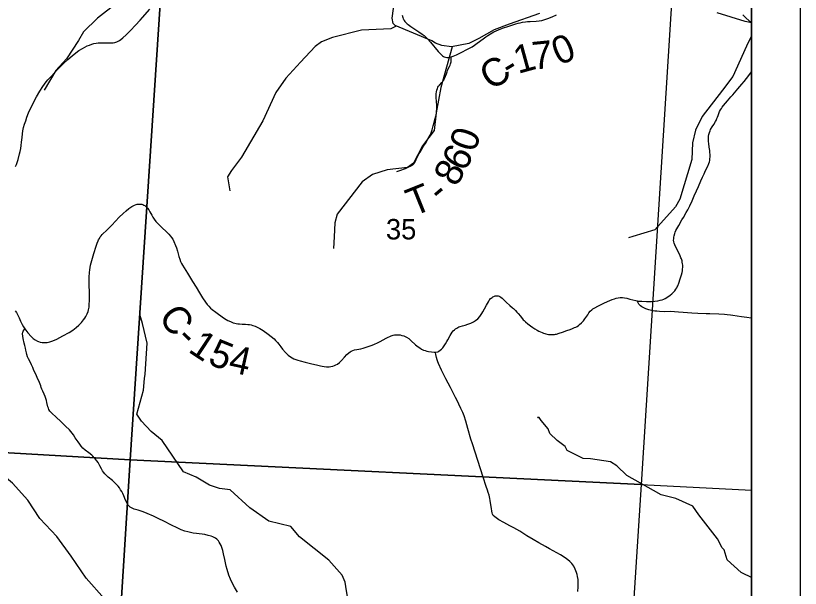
# Model space of a CAD drawing. Extents: x -2.1 to 31.9, y 6.3 to 28.3.
# Drawn here: x 5.327 to 6.934, y 23.525 to 24.699 of the extents above; entities that cross this region are included whole.
import ezdxf

# ---------------------------------------------------------------- set-up
doc = ezdxf.new("R2010")
doc.units = 0
for name, color, linetype in [('Default', 7, 'Continuous'), ('GM_X_County_Road', 7, 'Continuous'), ('GM_X_County_Road_Text', 7, 'Continuous'), ('GM_X_Minor_River', 7, 'Continuous'), ('GM_X_Section', 7, 'Continuous'), ('GM_X_Section_Text', 7, 'Continuous'), ('GM_X_Township_Road', 7, 'Continuous'), ('GM_X_Township_Road_Text', 7, 'Continuous'), ('SH_Cut_Line', 7, 'Continuous'), ('SH_Data', 7, 'Continuous')]:
    doc.layers.add(name, color=color, linetype=linetype)

msp = doc.modelspace()

# ---------------------------------------------------------------- linework, layer by layer
at = {"layer": 'Default'}
msp.add_lwpolyline([(6.8344, 20.444), (6.8344, 25.7721), (5.5694, 25.8349), (4.6286, 25.8765), (4.6032, 25.4816), (4.5667, 24.9084), (4.5473, 24.5954), (4.4901, 23.6442), (4.4651, 23.2405)], dxfattribs=at)
msp.add_lwpolyline([(6.8344, 23.7263), (6.8344, 24.7715), (6.674, 24.7794), (6.6083, 23.7379)], close=True, dxfattribs=at)
at = {"layer": 'GM_X_County_Road'}
for points in [[(5.3265, 24.3899), (5.3282, 24.3943), (5.3315, 24.4045), (5.3346, 24.416), (5.3358, 24.4209), (5.337, 24.4268), (5.3379, 24.4331), (5.3388, 24.4399), (5.3398, 24.4493), (5.3406, 24.4571), (5.3413, 24.4628), (5.3421, 24.4667), (5.3428, 24.47), (5.3448, 24.4766), (5.3472, 24.4837), (5.3497, 24.4911), (5.3529, 24.4997), (5.3554, 24.5059), (5.3588, 24.5126), (5.3623, 24.5197), (5.3694, 24.5331), (5.376, 24.5443), (5.3823, 24.5543), (5.3855, 24.5591), (5.3888, 24.5634), (5.3924, 24.5676), (5.399, 24.5746), (5.4125, 24.5887), (5.4251, 24.6016), (5.4337, 24.6096), (5.4421, 24.6169), (5.4498, 24.6232), (5.4562, 24.6277), (5.4635, 24.6322), (5.4686, 24.6349), (5.4734, 24.6372), (5.478, 24.6389), (5.4825, 24.6405), (5.4868, 24.6418), (5.4912, 24.6428), (5.4953, 24.6432), (5.4996, 24.6435), (5.5062, 24.6435), (5.5186, 24.6432), (5.5234, 24.6432), (5.5266, 24.6434), (5.5297, 24.644), (5.5319, 24.6446), (5.5341, 24.6456), (5.5364, 24.6467), (5.5392, 24.6483), (5.5421, 24.6504), (5.5459, 24.6535), (5.5529, 24.6601), (5.5617, 24.6687), (5.5723, 24.6797), (5.5814, 24.6897), (5.5863, 24.6954), (5.6013, 24.7128)], [(6.1184, 24.7002), (6.1202, 24.6951), (6.1209, 24.693), (6.1219, 24.691), (6.123, 24.6891), (6.1242, 24.6873), (6.1254, 24.6858), (6.1269, 24.6842), (6.1285, 24.6826), (6.1306, 24.6809), (6.1361, 24.6769), (6.1427, 24.6726), (6.1529, 24.6662), (6.1595, 24.6616), (6.1639, 24.6582), (6.1671, 24.6554), (6.1715, 24.6511), (6.1768, 24.6451), (6.1925, 24.6258), (6.1971, 24.6207), (6.1993, 24.6186), (6.2012, 24.617), (6.2031, 24.6158), (6.2049, 24.615), (6.2074, 24.6142), (6.2099, 24.6137), (6.2126, 24.6137), (6.2158, 24.6141), (6.2192, 24.6149), (6.2231, 24.6163), (6.2296, 24.6191), (6.2368, 24.6223), (6.2551, 24.6317), (6.2617, 24.6352), (6.267, 24.6385), (6.2726, 24.6425), (6.2844, 24.6517), (6.2898, 24.6558), (6.2939, 24.6586), (6.2996, 24.6621), (6.3067, 24.6658), (6.3157, 24.6699), (6.3244, 24.6733), (6.3372, 24.6779), (6.3513, 24.6826), (6.3561, 24.6839), (6.3604, 24.6848), (6.3652, 24.6857), (6.3712, 24.6867), (6.3755, 24.687), (6.3811, 24.6874), (6.3929, 24.6876), (6.3992, 24.6883), (6.4047, 24.6894), (6.4108, 24.6911), (6.4172, 24.6934), (6.4259, 24.6971), (6.4349, 24.7012)], [(6.8165, 24.7006), (6.823, 24.6946), (6.8298, 24.6886), (6.8344, 24.685)], [(6.1869, 24.0096), (6.1877, 24.0096), (6.1914, 24.0104), (6.1939, 24.0115), (6.1966, 24.0132), (6.1992, 24.0156), (6.2018, 24.0186), (6.2048, 24.0226), (6.2076, 24.0268), (6.2101, 24.031), (6.2123, 24.0347), (6.2171, 24.0438), (6.2192, 24.0471), (6.2211, 24.0502), (6.2233, 24.053), (6.2255, 24.0552), (6.2276, 24.057), (6.2303, 24.0589), (6.2326, 24.0602), (6.2348, 24.0611), (6.2376, 24.0621), (6.2421, 24.0635), (6.2477, 24.065), (6.2531, 24.0665), (6.2594, 24.0689), (6.2649, 24.0715), (6.269, 24.0741), (6.2733, 24.0775), (6.2778, 24.0824), (6.282, 24.0884), (6.2839, 24.0919), (6.2874, 24.0981), (6.2913, 24.1057), (6.2952, 24.1128), (6.2971, 24.1157), (6.2984, 24.1174), (6.2999, 24.1191), (6.3012, 24.1203), (6.3028, 24.1217), (6.3045, 24.1227), (6.3062, 24.1236), (6.3077, 24.1243), (6.3093, 24.1248), (6.3106, 24.125), (6.312, 24.1251), (6.3131, 24.1251), (6.3142, 24.125), (6.3156, 24.1248), (6.3171, 24.1243), (6.3188, 24.1235), (6.3207, 24.1222), (6.3233, 24.1199), (6.3261, 24.1174), (6.3318, 24.1116), (6.3392, 24.1049), (6.3445, 24.1004), (6.3465, 24.0987), (6.3486, 24.0967), (6.3506, 24.0948), (6.3535, 24.0916), (6.3563, 24.0885), (6.3608, 24.0831), (6.3667, 24.0759), (6.3685, 24.074), (6.3714, 24.0713), (6.376, 24.0674), (6.3814, 24.0633), (6.3862, 24.0601), (6.3906, 24.0572), (6.3949, 24.0547), (6.3986, 24.0527), (6.4053, 24.0495), (6.4081, 24.0484), (6.411, 24.0474), (6.4131, 24.0468), (6.4158, 24.0463), (6.4183, 24.0459), (6.421, 24.0456), (6.424, 24.0454), (6.4271, 24.0454), (6.4305, 24.0457), (6.4326, 24.046), (6.4349, 24.0466), (6.4403, 24.0483), (6.4471, 24.0506), (6.4558, 24.0536), (6.4627, 24.0561), (6.4673, 24.0578), (6.472, 24.0597), (6.4744, 24.0608), (6.4771, 24.0623), (6.4797, 24.0639), (6.4823, 24.0659), (6.4863, 24.0694), (6.4899, 24.0735), (6.4929, 24.0774), (6.4987, 24.086), (6.5013, 24.0901), (6.5039, 24.0934), (6.5069, 24.096), (6.5094, 24.0979), (6.5136, 24.1005), (6.5196, 24.1036), (6.5238, 24.1056), (6.5321, 24.1096), (6.5394, 24.1132), (6.5486, 24.1171), (6.5536, 24.119), (6.5573, 24.12), (6.5611, 24.1209), (6.5653, 24.1214), (6.5704, 24.1212), (6.5741, 24.1207), (6.5792, 24.1198), (6.5854, 24.1183), (6.5915, 24.1167), (6.5974, 24.1152), (6.6004, 24.1146), (6.6026, 24.1142), (6.6096, 24.1136), (6.6191, 24.113), (6.6237, 24.113), (6.6298, 24.1131), (6.6365, 24.1137), (6.6428, 24.1149), (6.6471, 24.1158), (6.6512, 24.1169), (6.6547, 24.1182), (6.6576, 24.1197), (6.6608, 24.1215), (6.6678, 24.1263), (6.6711, 24.1291), (6.6736, 24.1314), (6.677, 24.1352), (6.6796, 24.1387), (6.6811, 24.141), (6.6823, 24.1435), (6.6834, 24.1457), (6.6853, 24.1505), (6.6884, 24.1597), (6.6911, 24.1681), (6.6923, 24.1726), (6.6928, 24.1759), (6.6932, 24.1794), (6.6935, 24.1835), (6.6935, 24.1877), (6.6932, 24.1906), (6.6926, 24.194), (6.6921, 24.1964), (6.6916, 24.1984), (6.6907, 24.2009), (6.6897, 24.2031), (6.6873, 24.2086), (6.6836, 24.2161), (6.6774, 24.2293), (6.676, 24.233), (6.6753, 24.2354), (6.6749, 24.239), (6.6751, 24.242), (6.6754, 24.2449), (6.676, 24.2482), (6.6774, 24.2527), (6.6782, 24.2556), (6.6794, 24.2585), (6.6813, 24.2623), (6.6854, 24.2693), (6.6917, 24.2804), (6.6948, 24.2856), (6.7005, 24.2954), (6.7038, 24.3014), (6.7059, 24.3055), (6.7078, 24.3095), (6.7125, 24.3196), (6.7171, 24.3296), (6.7218, 24.3402), (6.7257, 24.3489), (6.7307, 24.3605), (6.7342, 24.3684), (6.7373, 24.3748), (6.7405, 24.3817), (6.7447, 24.391), (6.7469, 24.3961), (6.7481, 24.3995), (6.7488, 24.4026), (6.7493, 24.4059), (6.7495, 24.4096), (6.7495, 24.4138), (6.7493, 24.4192), (6.7488, 24.4229), (6.7477, 24.4297), (6.7467, 24.4368), (6.7463, 24.441), (6.7461, 24.4448), (6.7461, 24.4477), (6.7465, 24.4525), (6.7469, 24.4553), (6.7481, 24.4597), (6.7494, 24.4631), (6.7507, 24.466), (6.7537, 24.4711), (6.7569, 24.4764), (6.7604, 24.482), (6.7619, 24.4846), (6.7636, 24.4884), (6.7647, 24.4911), (6.7659, 24.4947), (6.7672, 24.4983), (6.7682, 24.5005), (6.769, 24.5025), (6.7707, 24.506), (6.7728, 24.5092), (6.7746, 24.5119), (6.7772, 24.5153), (6.7851, 24.5247), (6.7923, 24.5327), (6.7963, 24.5372), (6.8063, 24.5493), (6.8149, 24.5591), (6.8196, 24.5642), (6.8244, 24.5701), (6.8313, 24.5796), (6.8344, 24.5839)], [(5.3255, 24.0943), (5.3283, 24.0905), (5.331, 24.0854), (5.3336, 24.0797), (5.3367, 24.0727), (5.3398, 24.0663), (5.3424, 24.0615), (5.3451, 24.0573), (5.3515, 24.0491), (5.358, 24.0418), (5.3625, 24.0376), (5.3664, 24.0348), (5.3711, 24.0322), (5.3736, 24.0311), (5.3767, 24.0301), (5.3806, 24.0292), (5.3848, 24.0291), (5.3883, 24.0292), (5.3912, 24.0295), (5.3965, 24.0307), (5.4029, 24.0327), (5.4107, 24.0363), (5.4229, 24.0426), (5.436, 24.0496), (5.4438, 24.0545), (5.4507, 24.0597), (5.4562, 24.0646), (5.4617, 24.0704), (5.4659, 24.0756), (5.4683, 24.079), (5.4702, 24.0824), (5.4733, 24.0883), (5.475, 24.0929), (5.476, 24.0965), (5.4769, 24.1017), (5.4773, 24.1061), (5.4777, 24.1158), (5.4777, 24.1284), (5.4775, 24.1507), (5.4774, 24.1634), (5.4778, 24.1726), (5.4783, 24.178), (5.4791, 24.183), (5.4801, 24.188), (5.4826, 24.1971), (5.4868, 24.2114), (5.4914, 24.2264), (5.4934, 24.2325), (5.4953, 24.2373), (5.4966, 24.2398), (5.4981, 24.2426), (5.5, 24.2456), (5.5016, 24.2476), (5.5041, 24.2503), (5.5144, 24.2603), (5.5204, 24.2665), (5.5234, 24.2697), (5.5386, 24.2861), (5.5467, 24.2939), (5.5528, 24.2993), (5.5583, 24.3038), (5.5623, 24.3067), (5.5649, 24.3083), (5.5676, 24.3097), (5.5703, 24.3109), (5.5732, 24.312), (5.5754, 24.3125), (5.5781, 24.3129), (5.5812, 24.313), (5.5851, 24.3125), (5.5872, 24.3119), (5.5891, 24.311), (5.591, 24.3099), (5.5934, 24.3083), (5.595, 24.3068), (5.5968, 24.3048), (5.5993, 24.3011), (5.6014, 24.2974), (5.6053, 24.2902), (5.6078, 24.2859), (5.6105, 24.2818), (5.6138, 24.2774), (5.6179, 24.2729), (5.6269, 24.2645), (5.6351, 24.2568), (5.6404, 24.2514), (5.644, 24.2471), (5.6461, 24.2445), (5.6483, 24.2411), (5.6507, 24.2364), (5.6544, 24.2278), (5.656, 24.2234), (5.6583, 24.2161), (5.6612, 24.2056), (5.6629, 24.2), (5.6646, 24.1953), (5.6664, 24.1912), (5.6685, 24.1876), (5.6787, 24.1714), (5.6892, 24.1545), (5.6963, 24.1428), (5.7032, 24.131), (5.7094, 24.121), (5.7157, 24.1117), (5.7191, 24.1074), (5.7226, 24.1035), (5.726, 24.0999), (5.7292, 24.097), (5.7364, 24.0914), (5.7421, 24.0871), (5.7544, 24.0787), (5.7613, 24.0746), (5.7668, 24.072), (5.7725, 24.0696), (5.7757, 24.0688), (5.7787, 24.0681), (5.7819, 24.0677), (5.7849, 24.0674), (5.7907, 24.0671), (5.7973, 24.0668), (5.8025, 24.0664), (5.806, 24.0658), (5.8094, 24.0652), (5.8129, 24.0642), (5.817, 24.0627), (5.8215, 24.0606), (5.827, 24.0578), (5.8335, 24.054), (5.8443, 24.0466), (5.8503, 24.0418), (5.8565, 24.0364), (5.8591, 24.0335), (5.863, 24.0295), (5.8659, 24.0258), (5.8696, 24.0206), (5.8735, 24.0154), (5.8796, 24.0084), (5.8822, 24.0057), (5.8852, 24.0031), (5.8879, 24.001), (5.893, 23.9976), (5.8965, 23.9958), (5.9004, 23.9943), (5.9046, 23.9929), (5.9095, 23.9916), (5.9195, 23.9892), (5.9333, 23.9857), (5.9432, 23.9831), (5.9509, 23.9811), (5.9545, 23.9804), (5.9585, 23.9799), (5.9636, 23.9796), (5.969, 23.9796), (5.9726, 23.98), (5.9762, 23.9807), (5.9797, 23.9819), (5.9828, 23.9832), (5.9861, 23.985), (5.9899, 23.988), (5.9943, 23.9922), (6.0003, 23.9988), (6.0053, 24.0046), (6.0091, 24.008), (6.0118, 24.01), (6.0143, 24.0115), (6.0174, 24.0128), (6.021, 24.0139), (6.0256, 24.0148), (6.0337, 24.0164), (6.0389, 24.0177), (6.0451, 24.0194), (6.0509, 24.0214), (6.0574, 24.0236), (6.0617, 24.0255), (6.0678, 24.0283), (6.0733, 24.0311), (6.0799, 24.0348), (6.0856, 24.0379), (6.0896, 24.04), (6.093, 24.0418), (6.0962, 24.0431), (6.0999, 24.0442), (6.103, 24.0448), (6.1068, 24.0452), (6.1107, 24.0452), (6.1142, 24.0447), (6.1181, 24.0438), (6.1221, 24.0426), (6.1246, 24.0415), (6.1273, 24.0401), (6.1319, 24.0371), (6.1365, 24.0334), (6.1462, 24.0246), (6.1512, 24.0205), (6.1545, 24.0182), (6.1584, 24.0157), (6.1623, 24.0137), (6.1657, 24.0125), (6.1688, 24.0116), (6.1723, 24.0109), (6.179, 24.01), (6.1844, 24.0095), (6.1869, 24.0096)]]:
    msp.add_lwpolyline(points, dxfattribs=at)
at = {"layer": 'GM_X_Minor_River'}
for points in [[(6.4002, 24.7037), (6.3378, 24.6819), (6.3072, 24.6704), (6.2755, 24.6521), (6.2551, 24.6422), (6.2199, 24.6352), (6.1999, 24.6378), (6.187, 24.6431), (6.1791, 24.6473), (6.1042, 24.6787), (6.1004, 24.6829), (6.0982, 24.6942), (6.1045, 24.7395)], [(5.5337, 24.7245), (5.4945, 24.6944), (5.4654, 24.6658), (5.4556, 24.6483), (5.4306, 24.6106), (5.4091, 24.587), (5.3853, 24.5463)], [(6.8344, 24.6848), (6.8217, 24.6872), (6.7639, 24.7049)], [(6.1062, 24.6778), (6.0954, 24.6725), (6.0351, 24.6695), (5.9755, 24.6547), (5.9531, 24.6453), (5.9406, 24.6359), (5.9104, 24.6042), (5.8803, 24.5709), (5.8597, 24.5414), (5.8332, 24.4834), (5.7892, 24.4092), (5.7686, 24.3819), (5.7609, 24.3691), (5.7657, 24.3402)], [(6.8344, 24.6576), (6.8242, 24.6364), (6.7962, 24.5746), (6.7749, 24.5464), (6.7336, 24.4923), (6.7195, 24.4643), (6.7135, 24.4383), (6.7124, 24.4041), (6.6873, 24.3233), (6.6785, 24.3073), (6.6366, 24.2604), (6.5912, 24.2466), (6.5821, 24.2435)], [(6.2211, 24.6355), (6.1975, 24.552), (6.188, 24.5003), (6.1843, 24.4639), (6.1599, 24.4321), (6.1418, 24.3966), (6.1298, 24.3882), (6.0877, 24.3831), (6.0579, 24.3734), (6.0363, 24.3589), (5.9855, 24.2922), (5.9805, 24.2745), (5.9792, 24.2457), (5.9777, 24.2218)], [(6.0159, 23.4483), (6.0032, 23.5288), (6.0016, 23.538), (5.9956, 23.5522), (5.9682, 23.5827), (5.9084, 23.6306), (5.8905, 23.652), (5.8455, 23.663), (5.8066, 23.69), (5.7658, 23.7274), (5.744, 23.73), (5.7237, 23.7367), (5.6966, 23.7528), (5.6705, 23.7642), (5.6271, 23.8283), (5.6039, 23.8469), (5.5841, 23.868), (5.5751, 23.8823), (5.5883, 23.9313), (5.5909, 23.9555), (5.5919, 23.9646), (5.5961, 24.0279), (5.5864, 24.068), (5.5809, 24.0864)], [(5.5084, 23.5036), (5.4707, 23.5459), (5.44, 23.5909), (5.4106, 23.6313), (5.3758, 23.6685), (5.3516, 23.7061), (5.3202, 23.7405), (5.3121, 23.7476), (5.2674, 23.809), (5.245, 23.8306), (5.2205, 23.8679), (5.1894, 23.9159), (5.1484, 23.9985), (5.1396, 24.0071), (5.1136, 24.06)], [(6.8344, 23.5477), (6.8163, 23.5561), (6.8133, 23.5576), (6.7845, 23.5838), (6.7785, 23.6043), (6.7743, 23.6084), (6.7645, 23.6267), (6.7266, 23.6756), (6.7145, 23.6938), (6.6793, 23.7093), (6.6495, 23.7169), (6.6071, 23.7411), (6.5791, 23.7566), (6.5587, 23.7763), (6.5458, 23.7847), (6.5046, 23.7906), (6.4895, 23.7917), (6.4774, 23.7974), (6.4728, 23.7997), (6.4566, 23.8076), (6.4528, 23.816), (6.4365, 23.8281), (6.4214, 23.8429), (6.4176, 23.852), (6.4032, 23.8695), (6.3994, 23.8755), (6.3968, 23.8748), (6.3979, 23.8774)]]:
    msp.add_lwpolyline(points, dxfattribs=at)
at = {"layer": 'GM_X_Section'}
for points in [[(4.5692, 24.8661), (5.6296, 24.8273), (5.5612, 23.7889), (4.5062, 23.8498)], [(6.674, 24.7794), (6.6083, 23.7379), (5.5612, 23.7889), (5.6296, 24.8273)], [(5.5612, 23.7889), (5.498, 22.7781), (4.4397, 22.818), (4.4401, 22.8231), (4.4518, 23.0046), (4.4791, 23.4295), (4.5062, 23.8498)], [(6.6083, 23.7379), (6.5918, 23.4837), (6.5759, 23.2313), (6.5607, 22.9782), (6.5442, 22.7242), (6.4695, 22.728), (6.3902, 22.7322), (6.313, 22.7362), (6.2319, 22.7402), (6.1513, 22.7445), (6.0723, 22.7483), (5.9912, 22.7527), (5.9044, 22.7576), (5.8324, 22.7612), (5.7467, 22.7656), (5.664, 22.7698), (5.5827, 22.774), (5.498, 22.7781), (5.5612, 23.7889)]]:
    msp.add_lwpolyline(points, close=True, dxfattribs=at)
at = {"layer": 'GM_X_Township_Road'}
for points in [[(6.1075, 24.38), (6.1096, 24.3804), (6.1116, 24.3809), (6.1141, 24.3816), (6.1254, 24.3861), (6.1307, 24.3884), (6.1353, 24.3906), (6.1387, 24.3924), (6.1404, 24.3936), (6.1423, 24.3955), (6.1444, 24.3984), (6.1475, 24.4041), (6.1496, 24.4083), (6.1535, 24.4165), (6.1565, 24.4215), (6.159, 24.4258), (6.1625, 24.4316), (6.1662, 24.4373), (6.1691, 24.442), (6.172, 24.4472), (6.1739, 24.4505), (6.176, 24.4544), (6.178, 24.459), (6.1787, 24.4609), (6.1793, 24.4631), (6.18, 24.4654), (6.1822, 24.4732), (6.1842, 24.4802), (6.1857, 24.486), (6.1874, 24.4929), (6.1881, 24.4962), (6.1887, 24.4996), (6.1891, 24.5035), (6.1893, 24.5077), (6.1893, 24.5107), (6.1894, 24.5147), (6.1885, 24.5315), (6.1882, 24.5353), (6.1882, 24.5387), (6.1887, 24.543), (6.1895, 24.5466), (6.1907, 24.5499), (6.192, 24.5525), (6.1933, 24.5546), (6.1948, 24.5566), (6.2, 24.5621), (6.2016, 24.564), (6.2027, 24.5653), (6.2039, 24.5672), (6.2048, 24.5688), (6.2063, 24.5718), (6.2092, 24.5802), (6.2105, 24.5839), (6.2116, 24.5869), (6.213, 24.59), (6.2156, 24.5951), (6.2168, 24.598), (6.2178, 24.6005), (6.2186, 24.6026), (6.219, 24.6048), (6.2192, 24.6075), (6.2192, 24.6149)], [(6.8344, 24.0788), (6.8336, 24.079), (6.8248, 24.0804), (6.8141, 24.082), (6.7964, 24.0844), (6.7914, 24.085), (6.7845, 24.0858), (6.779, 24.0863), (6.7672, 24.0871), (6.7493, 24.088), (6.7418, 24.0883), (6.7245, 24.0889), (6.7121, 24.0895), (6.6941, 24.0909), (6.6849, 24.0915), (6.6767, 24.0921), (6.668, 24.0925), (6.6554, 24.0924), (6.646, 24.0929), (6.6406, 24.0931), (6.6365, 24.0936), (6.6298, 24.0945), (6.6238, 24.0959), (6.6179, 24.0979), (6.6135, 24.1), (6.6099, 24.1023), (6.6067, 24.1045), (6.6048, 24.1062), (6.6034, 24.108), (6.602, 24.1106), (6.6004, 24.1146)], [(5.3709, 23.9574), (5.3694, 23.9611), (5.3633, 23.9738), (5.3615, 23.9778), (5.3588, 23.9833), (5.356, 23.9895), (5.3531, 23.9956), (5.3511, 24.0001), (5.3495, 24.0045), (5.3487, 24.0078), (5.3475, 24.0132), (5.3466, 24.0175), (5.3456, 24.0228), (5.3443, 24.0276), (5.342, 24.0371), (5.3411, 24.042), (5.3409, 24.047), (5.3414, 24.0501), (5.3422, 24.0522), (5.3441, 24.0555), (5.3451, 24.0573)], [(6.4785, 23.5185), (6.479, 23.5281), (6.4793, 23.536), (6.4789, 23.5431), (6.4781, 23.5497), (6.4772, 23.5538), (6.4759, 23.5578), (6.4733, 23.5643), (6.4701, 23.5704), (6.466, 23.576), (6.4623, 23.5802), (6.4583, 23.5839), (6.4527, 23.5878), (6.4427, 23.594), (6.4205, 23.6064), (6.412, 23.6111), (6.3985, 23.6185), (6.3869, 23.6252), (6.3743, 23.633), (6.3594, 23.6421), (6.3477, 23.649), (6.3395, 23.6534), (6.327, 23.6602), (6.3166, 23.6658), (6.3111, 23.6695), (6.3083, 23.6715), (6.3053, 23.6748), (6.3036, 23.6775), (6.3029, 23.6799), (6.3022, 23.6833), (6.3014, 23.6886), (6.3004, 23.6965), (6.2991, 23.7054), (6.2984, 23.7094), (6.2977, 23.7127), (6.2967, 23.7159), (6.2951, 23.7214), (6.2934, 23.7267), (6.291, 23.7339), (6.2844, 23.7533), (6.2626, 23.8214), (6.2594, 23.8312), (6.2532, 23.8526), (6.2488, 23.8678), (6.2453, 23.8787), (6.2426, 23.8859), (6.2391, 23.894), (6.2348, 23.9029), (6.231, 23.9106), (6.228, 23.9166), (6.2174, 23.9371), (6.2082, 23.9544), (6.2039, 23.9632), (6.1993, 23.9726), (6.1932, 23.986), (6.1916, 23.9899), (6.1904, 23.9935), (6.1892, 23.9982), (6.1878, 24.0045), (6.1871, 24.0086), (6.1869, 24.0096)], [(5.7813, 23.5176), (5.7751, 23.5277), (5.7697, 23.5379), (5.767, 23.5437), (5.7637, 23.5521), (5.76, 23.5639), (5.7582, 23.5704), (5.7564, 23.5776), (5.7549, 23.5845), (5.7527, 23.5957), (5.7511, 23.6031), (5.7493, 23.6092), (5.7477, 23.6133), (5.7458, 23.6167), (5.7439, 23.6199), (5.7421, 23.6223), (5.7386, 23.6259), (5.7361, 23.6279), (5.7334, 23.6295), (5.7307, 23.6306), (5.727, 23.632), (5.7211, 23.6337), (5.7142, 23.6354), (5.6968, 23.6378), (5.6905, 23.6386), (5.6849, 23.6395), (5.6795, 23.6408), (5.6732, 23.6427), (5.6659, 23.6453), (5.6575, 23.649), (5.6456, 23.6547), (5.6303, 23.663), (5.6201, 23.6678), (5.6088, 23.673), (5.5961, 23.6786), (5.5881, 23.682), (5.5773, 23.6855), (5.5695, 23.6878), (5.5651, 23.6896), (5.5611, 23.6919), (5.558, 23.6949), (5.5557, 23.6977), (5.5542, 23.7006), (5.5518, 23.7061), (5.5482, 23.7149), (5.5462, 23.7196), (5.5439, 23.7239), (5.5417, 23.7273), (5.5392, 23.7311), (5.5365, 23.7345), (5.5333, 23.7384), (5.5292, 23.7424), (5.5248, 23.7461), (5.5163, 23.7533), (5.5126, 23.7566), (5.5093, 23.7601), (5.5067, 23.7636), (5.5047, 23.7664), (5.5027, 23.7699), (5.4989, 23.7766), (5.4953, 23.7829), (5.4929, 23.7863), (5.4896, 23.7906), (5.4874, 23.7931), (5.4846, 23.796), (5.4823, 23.7981), (5.4762, 23.8027), (5.4687, 23.8084), (5.4641, 23.8128), (5.4608, 23.8169), (5.4579, 23.8207), (5.4544, 23.8253), (5.4485, 23.834), (5.4449, 23.8396), (5.4424, 23.8433), (5.4369, 23.8501), (5.429, 23.858), (5.4185, 23.8678), (5.4102, 23.8753), (5.3999, 23.8847), (5.3969, 23.8882), (5.3948, 23.8918), (5.3936, 23.8945), (5.3927, 23.8972), (5.3906, 23.9062), (5.3895, 23.9105), (5.3884, 23.9145), (5.3871, 23.9182), (5.3851, 23.9234), (5.3821, 23.9295), (5.3802, 23.9335), (5.3791, 23.9368), (5.3781, 23.9401), (5.3768, 23.944), (5.3753, 23.9473), (5.3709, 23.9574)]]:
    msp.add_lwpolyline(points, dxfattribs=at)
at = {"layer": 'SH_Cut_Line'}
msp.add_lwpolyline([(6.8344, 20.444), (6.8344, 27.244), (0.0344, 27.244), (0.0344, 20.444)], dxfattribs=at)
at = {"layer": 'SH_Data'}
for p, q in [((6.9344, 27.344), (6.9344, 20.344)), ((6.8344, 27.244), (6.8344, 20.444))]:
    msp.add_line(p, q, dxfattribs=at)

# ---------------------------------------------------------------- texts
at = {"layer": 'GM_X_County_Road_Text'}
for s, rotation, p in [('7', 5.6189, (6.3871, 24.5884)), ('0', 22.8253, (6.4399, 24.5964)), ('1', 15.4032, (6.3558, 24.5796)), ('C', 32.0401, (6.3002, 24.5446)), ('-', 30.8138, (6.3395, 24.5692)), ('C', 304.4998, (5.6178, 24.0825)), ('-', 316.1355, (5.6524, 24.0345)), ('1', 326.5173, (5.678, 24.0113)), ('5', 337.7555, (5.7179, 23.9863)), ('4', 347.5203, (5.7604, 23.9699))]:
    msp.add_text(s, height=0.0568, rotation=rotation, dxfattribs=at).set_placement(p)
at = {"layer": 'GM_X_Section_Text'}
msp.add_text('35', height=0.04186, rotation=0, dxfattribs=at).set_placement((6.0853, 24.2405))
at = {"layer": 'GM_X_Township_Road_Text'}
for s, rotation, p in [('0', 70.935, (6.2674, 24.4173)), ('6', 61.4261, (6.2465, 24.3772)), ('8', 62.0232, (6.2302, 24.3464)), ('T', 21.8814, (6.1413, 24.2871)), ('-', 39.982, (6.1974, 24.313))]:
    msp.add_text(s, height=0.0568, rotation=rotation, dxfattribs=at).set_placement(p)

doc.saveas('drawing.dxf')
